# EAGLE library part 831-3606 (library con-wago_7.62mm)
Serie 831, Stiftleiste (für Leiterplatten) mit geraden Einlötstiften / Series 831, Male header (for PCBs) with straight solder pins Polzahl / Pole No.: 6 Bemessungsspannung / Rated Voltage: 630 V Nennstrom / Nominal Current: 41 A Lötstiftlänge: / Solder Pin Length: 4 mm Farbe / Color: lichtgrau / light gray Stand: 01.01.2012. Die jeweils aktuellen Daten zu diesem Artikel finden Sie in unserem Produktkatalog, den Sie unter www.wago.com einsehen können. As of: 01/01/2012. Please find the newest data for this article in our product catalogue, which can be viewed under www.wago.com.
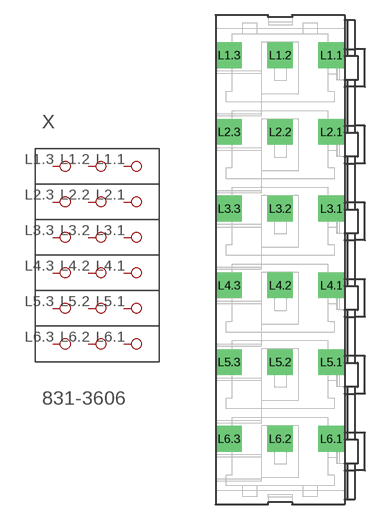
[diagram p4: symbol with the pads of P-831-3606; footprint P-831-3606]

Designator prefix X

## 831-3606  [P-831-3606]
L1.1  P1.1
L1.2  P1.2
L1.3  P1.3
L2.1  P2.1
L2.2  P2.2
L2.3  P2.3
L3.1  P3.1
L3.2  P3.2
L3.3  P3.3
L4.1  P4.1
L4.2  P4.2
L4.3  P4.3
L5.1  P5.1
L5.2  P5.2
L5.3  P5.3
L6.1  P6.1
L6.2  P6.2
L6.3  P6.3

## Footprint P-831-3606 (pad centres in mm)
drill 1.7 square: L1.1 4.08,20.32; L1.2 -1,20.32; L1.3 -6.08,20.32; L2.1 4.08,12.7; L2.2 -1,12.7; L2.3 -6.08,12.7; L3.1 4.08,5.08; L3.2 -1,5.08; L3.3 -6.08,5.08; L4.1 4.08,-2.54; L4.2 -1,-2.54; L4.3 -6.08,-2.54; L5.1 4.07,-10.16; L5.2 -1.01,-10.16; L5.3 -6.09,-10.16; L6.1 4.07,-17.78; L6.2 -1.01,-17.78; L6.3 -6.09,-17.78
